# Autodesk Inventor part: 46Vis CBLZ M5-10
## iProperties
Created: 2011-01
Part Number: 46Vis CBLZ M5-10
Document SubType Name: Modeling
Designer: eric
Density: 1 g/cm^3
Mass: 0.349554 g
Surface Area: 3.7092 cm^2
Volume: 0.349554 cm^3
Author: eric
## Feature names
1. Base1
